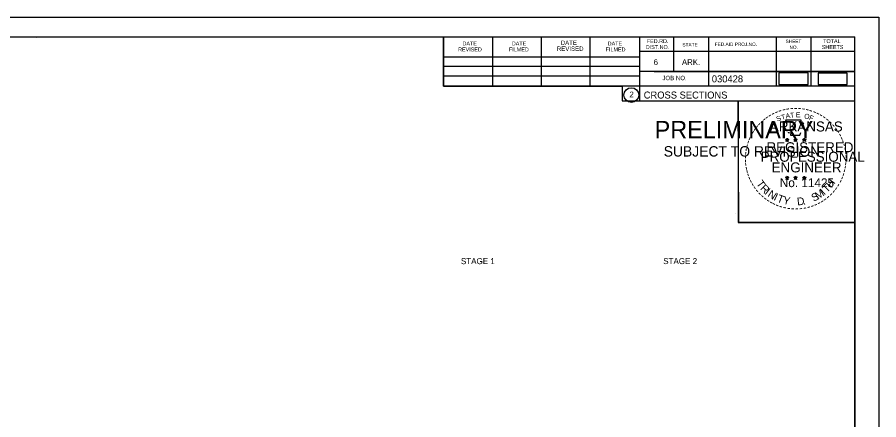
# Model space of a CAD drawing. Extents: x 1374859 to 1376773, y 382242 to 389804.
# Drawn here: x 1376125.3 to 1376297.5, y 383867.9 to 383948.4 of the extents above; entities that cross this region are included whole.
import ezdxf

# ---------------------------------------------------------------- set-up
doc = ezdxf.new("R2010")
doc.units = 0
for name, color, linetype in [('R_Axis Annot', 7, 'Continuous'), ('R_Border', 7, 'Continuous'), ('R_Border PE', 7, 'Continuous'), ('R_Border Prem', 7, 'Continuous'), ('R_MOT', 7, 'Continuous'), ('R_No Plot', 7, 'Continuous')]:
    doc.layers.add(name, color=color, linetype=linetype)

msp = doc.modelspace()

# ---------------------------------------------------------------- linework, layer by layer
at = {"layer": 'R_Border'}
for p, q in [((1375976.57, 383944.55), (1376292.75, 383944.55)), ((1376210.49, 383934.67), (1376210.49, 383944.55)), ((1376249.65, 383944.55), (1376249.65, 383931.75)), ((1376256.49, 383944.55), (1376256.49, 383937.61)), ((1376263.43, 383944.55), (1376263.43, 383934.67)), ((1376277.01, 383944.55), (1376277.01, 383934.67)), ((1376283.95, 383944.55), (1376283.95, 383934.67)), ((1376292.75, 383739.09), (1376292.75, 383944.55)), ((1376129.09, 383944.29), (1376129.09, 383944.29)), ((1376129.09, 383944.29), (1376129.09, 383944.29)), ((1376220.35, 383934.67), (1376220.35, 383944.35)), ((1376230.11, 383934.67), (1376230.11, 383944.35)), ((1376239.79, 383934.67), (1376239.79, 383944.35)), ((1376292.75, 383941.61), (1376249.65, 383941.61)), ((1376292.75, 383941.63), (1376292.75, 383941.63)), ((1376210.49, 383940.53), (1376249.65, 383940.53)), ((1376210.49, 383938.67), (1376249.65, 383938.67)), ((1376292.75, 383937.61), (1376249.65, 383937.61)), ((1376252.61, 383937.61), (1376292.75, 383937.61)), ((1376210.49, 383934.67), (1376210.49, 383936.73)), ((1376210.49, 383936.73), (1376249.65, 383936.73)), ((1376292.75, 383934.67), (1376210.49, 383934.67)), ((1376249.65, 383931.75), (1376292.75, 383931.75))]:
    msp.add_line(p, q, dxfattribs=at)
msp.add_circle((1376248.04, 383932.88), 1.47, dxfattribs=at)
at = {"layer": 'R_Border PE'}
for p, q in [((1376278.84, 383924), (1376279.18, 383923.89)), ((1376278.84, 383924), (1376279.09, 383923.96)), ((1376278.84, 383924), (1376279.07, 383923.88)), ((1376278.97, 383923.59), (1376279.18, 383923.89)), ((1376278.97, 383923.59), (1376279.09, 383923.84)), ((1376278.97, 383923.59), (1376279.18, 383923.81)), ((1376279.18, 383924.26), (1376279.14, 383924)), ((1376279.18, 383923.89), (1376279.18, 383924.26)), ((1376279.18, 383924.26), (1376279.23, 383924.01)), ((1376279.53, 383924), (1376279.18, 383923.89)), ((1376279.4, 383923.59), (1376279.18, 383923.89)), ((1376279.4, 383923.59), (1376279.18, 383923.81)), ((1376279.53, 383924), (1376279.25, 383923.95)), ((1376279.4, 383923.59), (1376279.26, 383923.88)), ((1376279.53, 383924), (1376279.33, 383923.9)), ((1376280.51, 383924), (1376280.85, 383923.89)), ((1376280.51, 383924), (1376280.76, 383923.96)), ((1376280.51, 383924), (1376280.74, 383923.88)), ((1376280.64, 383923.59), (1376280.85, 383923.89)), ((1376280.64, 383923.59), (1376280.76, 383923.84)), ((1376280.64, 383923.59), (1376280.85, 383923.81)), ((1376280.85, 383924.26), (1376280.81, 383924)), ((1376280.85, 383923.89), (1376280.85, 383924.26)), ((1376280.85, 383924.26), (1376280.9, 383924.01)), ((1376281.2, 383924), (1376280.85, 383923.89)), ((1376281.07, 383923.59), (1376280.85, 383923.89)), ((1376281.07, 383923.59), (1376280.85, 383923.81)), ((1376281.2, 383924), (1376280.92, 383923.95)), ((1376281.07, 383923.59), (1376280.93, 383923.88)), ((1376281.2, 383924), (1376281, 383923.9)), ((1376282.27, 383923.99), (1376282.62, 383923.88)), ((1376282.27, 383923.99), (1376282.52, 383923.94)), ((1376282.27, 383923.99), (1376282.51, 383923.87)), ((1376282.4, 383923.58), (1376282.62, 383923.88)), ((1376282.4, 383923.58), (1376282.53, 383923.83)), ((1376282.4, 383923.58), (1376282.62, 383923.8)), ((1376282.62, 383924.24), (1376282.58, 383923.99)), ((1376282.62, 383923.88), (1376282.62, 383924.24)), ((1376282.62, 383924.24), (1376282.67, 383923.99)), ((1376282.97, 383923.99), (1376282.62, 383923.88)), ((1376282.83, 383923.58), (1376282.62, 383923.88)), ((1376282.83, 383923.58), (1376282.62, 383923.8)), ((1376282.97, 383923.99), (1376282.68, 383923.94)), ((1376282.83, 383923.58), (1376282.69, 383923.87)), ((1376282.97, 383923.99), (1376282.76, 383923.89)), ((1376278.83, 383916.43), (1376279.18, 383916.32)), ((1376278.83, 383916.43), (1376279.08, 383916.38)), ((1376278.83, 383916.43), (1376279.07, 383916.31)), ((1376278.96, 383916.02), (1376279.18, 383916.32)), ((1376278.96, 383916.02), (1376279.09, 383916.26)), ((1376278.96, 383916.02), (1376279.18, 383916.24)), ((1376279.18, 383916.68), (1376279.14, 383916.43)), ((1376279.18, 383916.32), (1376279.18, 383916.68)), ((1376279.18, 383916.68), (1376279.23, 383916.43)), ((1376279.53, 383916.43), (1376279.18, 383916.32)), ((1376279.39, 383916.02), (1376279.18, 383916.32)), ((1376279.39, 383916.02), (1376279.18, 383916.23)), ((1376279.53, 383916.43), (1376279.24, 383916.38)), ((1376279.39, 383916.02), (1376279.26, 383916.31)), ((1376279.53, 383916.43), (1376279.32, 383916.33)), ((1376280.5, 383916.43), (1376280.85, 383916.32)), ((1376280.5, 383916.43), (1376280.75, 383916.38)), ((1376280.5, 383916.43), (1376280.74, 383916.31)), ((1376280.63, 383916.02), (1376280.85, 383916.32)), ((1376280.63, 383916.02), (1376280.76, 383916.26)), ((1376280.63, 383916.02), (1376280.85, 383916.24)), ((1376280.85, 383916.68), (1376280.81, 383916.43)), ((1376280.85, 383916.32), (1376280.85, 383916.68)), ((1376280.85, 383916.68), (1376280.9, 383916.43)), ((1376281.2, 383916.43), (1376280.85, 383916.32)), ((1376281.06, 383916.02), (1376280.85, 383916.32)), ((1376281.06, 383916.02), (1376280.85, 383916.23)), ((1376281.2, 383916.43), (1376280.91, 383916.38)), ((1376281.06, 383916.02), (1376280.93, 383916.31)), ((1376281.2, 383916.43), (1376280.99, 383916.33)), ((1376282.27, 383916.42), (1376282.62, 383916.31)), ((1376282.27, 383916.42), (1376282.52, 383916.37)), ((1376282.27, 383916.42), (1376282.5, 383916.3)), ((1376282.4, 383916.01), (1376282.62, 383916.31)), ((1376282.4, 383916.01), (1376282.53, 383916.25)), ((1376282.4, 383916.01), (1376282.61, 383916.23)), ((1376282.62, 383916.67), (1376282.58, 383916.42)), ((1376282.83, 383916.01), (1376282.61, 383916.22)), ((1376282.62, 383916.31), (1376282.62, 383916.67)), ((1376282.62, 383916.67), (1376282.67, 383916.42)), ((1376282.96, 383916.42), (1376282.62, 383916.31)), ((1376282.83, 383916.01), (1376282.62, 383916.31)), ((1376282.96, 383916.42), (1376282.68, 383916.37)), ((1376282.83, 383916.01), (1376282.69, 383916.3)), ((1376282.96, 383916.42), (1376282.76, 383916.32))]:
    msp.add_line(p, q, dxfattribs=at)
for points in [[(1376278.88, 383927.88), (1376279.15, 383927.05)], [(1376282.39, 383926.96), (1376282.53, 383927.24), (1376281.84, 383927.22), (1376281.99, 383927.88), (1376278.88, 383927.88)], [(1376279.18, 383924.26), (1376279.4, 383923.59), (1376278.84, 383924), (1376279.53, 383924), (1376278.97, 383923.59), (1376279.18, 383924.26)], [(1376279.37, 383925.46), (1376279.37, 383925.37), (1376279.93, 383925.35), (1376279.88, 383924.88), (1376281.75, 383924.88), (1376281.95, 383925.41)], [(1376280.85, 383924.26), (1376281.07, 383923.59), (1376280.51, 383924), (1376281.2, 383924), (1376280.64, 383923.59), (1376280.85, 383924.26)], [(1376282.62, 383924.24), (1376282.83, 383923.58), (1376282.27, 383923.99), (1376282.97, 383923.99), (1376282.4, 383923.58), (1376282.62, 383924.24)], [(1376279.18, 383916.68), (1376279.39, 383916.02), (1376278.83, 383916.43), (1376279.53, 383916.43), (1376278.96, 383916.02), (1376279.18, 383916.68)], [(1376280.85, 383916.68), (1376281.06, 383916.02), (1376280.5, 383916.43), (1376281.2, 383916.43), (1376280.63, 383916.02), (1376280.85, 383916.68)], [(1376282.62, 383916.67), (1376282.83, 383916.01), (1376282.27, 383916.42), (1376282.96, 383916.42), (1376282.4, 383916.01), (1376282.62, 383916.67)]]:
    msp.add_lwpolyline(points, dxfattribs=at)
for centre, radius in [((1376279.18, 383923.89), 0.172), ((1376279.18, 383923.89), 0.145), ((1376279.18, 383923.89), 0.116), ((1376279.18, 383923.89), 0.0991), ((1376279.18, 383923.89), 0.0747), ((1376279.18, 383923.89), 0.0495), ((1376279.18, 383923.89), 0.0296), ((1376280.85, 383923.89), 0.172), ((1376280.85, 383923.89), 0.145), ((1376280.85, 383923.89), 0.116), ((1376280.85, 383923.89), 0.0991), ((1376280.85, 383923.89), 0.0747), ((1376280.85, 383923.89), 0.0495), ((1376280.85, 383923.89), 0.0296), ((1376282.62, 383923.88), 0.172), ((1376282.62, 383923.88), 0.145), ((1376282.62, 383923.88), 0.116), ((1376282.62, 383923.88), 0.0991), ((1376282.62, 383923.88), 0.0747), ((1376282.62, 383923.88), 0.0495), ((1376282.62, 383923.88), 0.0296), ((1376279.18, 383916.32), 0.172), ((1376279.18, 383916.32), 0.145), ((1376279.18, 383916.32), 0.116), ((1376279.18, 383916.32), 0.0991), ((1376279.18, 383916.32), 0.0747), ((1376279.18, 383916.32), 0.0495), ((1376279.18, 383916.32), 0.0296), ((1376280.85, 383916.32), 0.172), ((1376280.85, 383916.32), 0.145), ((1376280.85, 383916.32), 0.116), ((1376280.85, 383916.32), 0.0991), ((1376280.85, 383916.32), 0.0747), ((1376280.85, 383916.32), 0.0495), ((1376280.85, 383916.32), 0.0296), ((1376282.62, 383916.31), 0.172), ((1376282.62, 383916.31), 0.145), ((1376282.62, 383916.31), 0.116), ((1376282.62, 383916.31), 0.0991), ((1376282.62, 383916.31), 0.0747), ((1376282.62, 383916.31), 0.0495), ((1376282.62, 383916.31), 0.0296)]:
    msp.add_circle(centre, radius, dxfattribs=at)
at = {"layer": 'R_MOT'}
for points in [[(1376277.55, 383935), (1376283.38, 383935), (1376283.38, 383937.31), (1376277.55, 383937.31)], [(1376285.38, 383934.97), (1376291.21, 383934.97), (1376291.21, 383937.28), (1376285.38, 383937.28)]]:
    msp.add_lwpolyline(points, close=True, dxfattribs=at)
at = {"layer": 'R_No Plot'}
for p, q in [((1375964.17, 383948.44), (1376297.5, 383948.44)), ((1376268.78, 383909.29), (1376268.78, 383909.29))]:
    msp.add_line(p, q, dxfattribs=at)
for points in [[(1375964.16, 383948.44), (1376297.5, 383948.44), (1376297.5, 383735.1), (1375964.16, 383735.1)], [(1376210.49, 383944.55), (1376210.49, 383934.67), (1376246.22, 383934.67), (1376246.22, 383931.75), (1376269.42, 383931.75), (1376269.42, 383907.41), (1376292.75, 383907.41), (1376292.75, 383739.09), (1375976.57, 383739.09), (1375976.57, 383944.55)], [(1376269.42, 383931.75), (1376292.63, 383931.75), (1376292.75, 383907.41), (1376269.54, 383907.41)]]:
    msp.add_lwpolyline(points, close=True, dxfattribs=at)

# ---------------------------------------------------------------- texts
at = {"layer": 'R_Axis Annot'}
for s, p in [('STAGE 1', (1376213.97, 383899.06)), ('STAGE 2', (1376254.41, 383899.07))]:
    msp.add_text(s, height=1.2, rotation=360, dxfattribs=at).set_placement(p)
at = {"layer": 'R_Border'}
for s, height, p in [('DATE', 0.782, (1376214.29, 383942.79)), ('DATE', 0.782, (1376224.15, 383942.79)), ('DATE', 0.879, (1376233.93, 383942.89)), ('DATE', 0.782, (1376243.31, 383942.79)), ('DIST.NO.', 0.782, (1376250.93, 383942.09)), ('FED.RD.', 0.782, (1376251.13, 383943.27)), ('STATE', 0.684, (1376258.25, 383942.59)), ('FED.AID PROJ.NO.', 0.684, (1376264.71, 383942.69)), ('SHEET', 0.684, (1376278.87, 383943.27)), ('NO.', 0.684, (1376279.65, 383942.09)), ('SHEETS', 0.782, (1376286.11, 383942.09)), ('TOTAL', 0.782, (1376286.39, 383943.27)), ('REVISED', 0.782, (1376213.41, 383941.61)), ('FILMED', 0.782, (1376223.57, 383941.61)), ('REVISED', 0.879, (1376233.15, 383941.71)), ('FILMED', 0.782, (1376242.91, 383941.61)), ('6', 1.17, (1376252.49, 383938.87)), ('ARK.', 1.172, (1376258.15, 383938.87)), ('JOB NO.', 0.879, (1376254.25, 383935.85)), ('030428', 1.4, (1376264.13, 383935.41)), ('2', 1.17, (1376247.65, 383932.4)), ('CROSS SECTIONS', 1.4, (1376250.51, 383932.18))]:
    msp.add_text(s, height=height, rotation=360, dxfattribs=at).set_placement(p)
at = {"layer": 'R_Border PE'}
for s, height, rotation, p in [('-', 1.6, 34.0636, (1376275.76, 383928.05)), ('-', 1.6, 28.7918, (1376276.36, 383928.42)), ('-', 1.6, 24.3072, (1376276.99, 383928.74)), ('-', 1.6, 19.1761, (1376277.62, 383929.01)), ('T', 1, 16.4036, (1376278.15, 383927.89)), ('-', 1.6, 13.6301, (1376278.37, 383929.25)), ('A', 1, 11.2132, (1376278.97, 383928.14)), ('-', 1.6, 10.2193, (1376279.05, 383929.41)), ('T', 1, 6.0228, (1376279.82, 383928.31)), ('-', 1.6, 5.8968, (1376279.78, 383929.52)), ('-', 1.6, 0.1862, (1376280.55, 383929.59)), ('E', 1, 0.8323, (1376280.93, 383928.42)), ('-', 1.6, 357.743, (1376281.28, 383929.58)), ('-', 1.6, 352.1617, (1376282.02, 383929.52)), ('O', 1, 350.4515, (1376282.53, 383928.21)), ('-', 1.6, 347.2049, (1376282.74, 383929.41)), ('-', 1.6, 342.3362, (1376283.37, 383929.25)), ('-', 1.6, 337.8551, (1376284.11, 383929.03)), ('-', 1.6, 334.1211, (1376284.74, 383928.76)), ('-', 1.6, 329.6409, (1376285.32, 383928.48)), ('-', 1.6, 48.423, (1376273.83, 383926.38)), ('-', 1.6, 42.9622, (1376274.27, 383926.86)), ('-', 1.6, 38.9507, (1376274.71, 383927.28)), ('-', 1.6, 36.2317, (1376275.18, 383927.66)), ('ARKANSAS', 2, 360, (1376275.73, 383925.59)), ('S', 1, 21.594, (1376277.23, 383927.56)), ('F', 1, 340.0707, (1376283.48, 383927.98)), ('-', 1.6, 325.8627, (1376285.96, 383928.12)), ('-', 1.6, 320.5297, (1376286.57, 383927.69)), ('-', 1.6, 315.5786, (1376287.17, 383927.2)), ('-', 1.6, 58.0706, (1376272.68, 383924.8)), ('-', 1.6, 54.2325, (1376273.01, 383925.33)), ('-', 1.6, 50.6142, (1376273.42, 383925.9)), ('-', 1.6, 309.8797, (1376287.74, 383926.65)), ('-', 1.6, 306.6522, (1376288.27, 383926.05)), ('-', 1.4, 303.6753, (1376288.75, 383925.48)), ('-', 1.6, 72.3945, (1376271.89, 383922.95)), ('-', 1.6, 67.7743, (1376272.11, 383923.58)), ('-', 1.6, 62.8713, (1376272.37, 383924.19)), ('DWB', 0.01, 360, (1376279.17, 383923.88)), ('DWB', 0.01, 360, (1376280.84, 383923.88)), ('DWB', 0.01, 360, (1376282.61, 383923.87)), ('-', 1.6, 299.6684, (1376289.07, 383924.87)), ('-', 1.6, 294.6628, (1376289.39, 383924.26)), ('-', 1.6, 290.5728, (1376289.65, 383923.69)), ('-', 1.6, 81.2013, (1376271.56, 383921.52)), ('-', 1.6, 75.461, (1376271.7, 383922.23)), ('REGISTERED', 2, 360, (1376275.05, 383921.44)), ('-', 1.6, 285.1233, (1376289.89, 383923.11)), ('-', 1.6, 280.5493, (1376290.09, 383922.36)), ('-', 1.6, 89.0622, (1376271.46, 383920.13)), ('-', 1.6, 85.1863, (1376271.49, 383920.83)), ('PROFESSIONAL', 2, 360, (1376273.9, 383919.54)), ('-', 1.6, 276.5962, (1376290.25, 383921.6)), ('-', 1.6, 274.3301, (1376290.31, 383920.87)), ('-', 1.6, 94.1959, (1376271.5, 383919.4)), ('-', 1.6, 98.9479, (1376271.57, 383918.74)), ('ENGINEER', 2, 360, (1376276.09, 383917.41)), ('-', 1.6, 260.9953, (1376290.25, 383918.92)), ('-', 1.6, 263.5172, (1376290.32, 383919.58)), ('-', 1.6, 269.9407, (1376290.34, 383920.24)), ('-', 1.6, 101.7149, (1376271.71, 383918)), ('-', 1.6, 105.4578, (1376271.87, 383917.41)), ('-', 1.6, 109.0874, (1376272.08, 383916.78)), ('-', 1.6, 252.8681, (1376289.96, 383917.52)), ('-', 1.6, 255.7626, (1376290.14, 383918.24)), ('-', 1.6, 114.0643, (1376272.34, 383916.18)), ('-', 1.6, 115.7289, (1376272.64, 383915.56)), ('-', 1.6, 120.4471, (1376273, 383914.98)), ('T', 1.54, 306.0406, (1376272.94, 383915.16)), ('No. 11425', 1.757, 360, (1376277.72, 383914.46)), ('DWB', 0.01, 360, (1376279.17, 383916.31)), ('DWB', 0.01, 360, (1376280.84, 383916.31)), ('DWB', 0.01, 360, (1376282.6, 383916.3)), ('T', 1.54, 46.6444, (1376287.17, 383913.25)), ('H', 1.54, 54.6088, (1376288.06, 383914.19)), ('-', 1.6, 244.6197, (1376289.48, 383916.22)), ('-', 1.6, 247.8887, (1376289.74, 383916.85)), ('-', 1.6, 125.8934, (1376273.4, 383914.42)), ('-', 1.6, 130.7181, (1376273.86, 383913.86)), ('R', 1.54, 314.005, (1376273.7, 383914.11)), ('I', 1.54, 321.9694, (1376274.6, 383913.18)), ('N', 1.54, 326.5002, (1376275.17, 383912.7)), ('M', 1.54, 32.6563, (1376285.32, 383911.92)), ('I', 1.54, 42.1136, (1376286.61, 383912.77)), ('-', 1.6, 231.2538, (1376288.25, 383914.25)), ('-', 1.6, 233.8452, (1376288.68, 383914.82)), ('-', 1.6, 239.0712, (1376289.08, 383915.47)), ('-', 1.6, 134.2238, (1376274.38, 383913.32)), ('-', 1.6, 138.9338, (1376274.91, 383912.86)), ('-', 1.6, 144.6463, (1376275.46, 383912.45)), ('-', 1.6, 148.0898, (1376276.02, 383912.08)), ('I', 1.54, 335.3603, (1376276.38, 383911.92)), ('T', 1.54, 339.8912, (1376277.04, 383911.59)), ('Y', 1.54, 347.8556, (1376278.26, 383911.15)), ('D', 1.54, 6.3969, (1376281.24, 383910.79)), ('S', 1.54, 26.9312, (1376284.49, 383911.52)), ('-', 1.6, 212.2491, (1376286.17, 383912.32)), ('-', 1.6, 215.7363, (1376286.7, 383912.71)), ('-', 1.6, 221.0851, (1376287.25, 383913.18)), ('-', 1.6, 225.7653, (1376287.77, 383913.69)), ('-', 1.6, 151.5704, (1376276.6, 383911.75)), ('-', 1.6, 154.6002, (1376277.12, 383911.51)), ('-', 1.6, 158.5612, (1376277.75, 383911.25)), ('-', 1.6, 162.7983, (1376278.43, 383911.04)), ('-', 1.6, 167.5555, (1376279.15, 383910.88)), ('-', 1.6, 173.1155, (1376279.92, 383910.77)), ('-', 1.6, 176.5183, (1376280.67, 383910.71)), ('-', 1.6, 181.5918, (1376281.41, 383910.73)), ('-', 1.6, 185.8167, (1376282.22, 383910.81)), ('-', 1.6, 191.2858, (1376282.96, 383910.94)), ('.', 1.54, 13.7642, (1376282.43, 383910.91)), ('-', 1.6, 195.4743, (1376283.69, 383911.14)), ('-', 1.6, 200.7184, (1376284.36, 383911.38)), ('-', 1.6, 204.2516, (1376284.98, 383911.65)), ('-', 1.6, 207.3568, (1376285.61, 383911.97))]:
    msp.add_text(s, height=height, rotation=rotation, dxfattribs=at).set_placement(p)
at = {"layer": 'R_Border Prem'}
for s, height, p in [('PRELIMINARY', 3.5, (1376252.7, 383924.21)), ('DWB', 0.01, (1376253.45, 383926.06)), ('SUBJECT TO REVISION', 2.0751, (1376254.51, 383920.58))]:
    msp.add_text(s, height=height, rotation=360, dxfattribs=at).set_placement(p)

doc.saveas('drawing.dxf')
